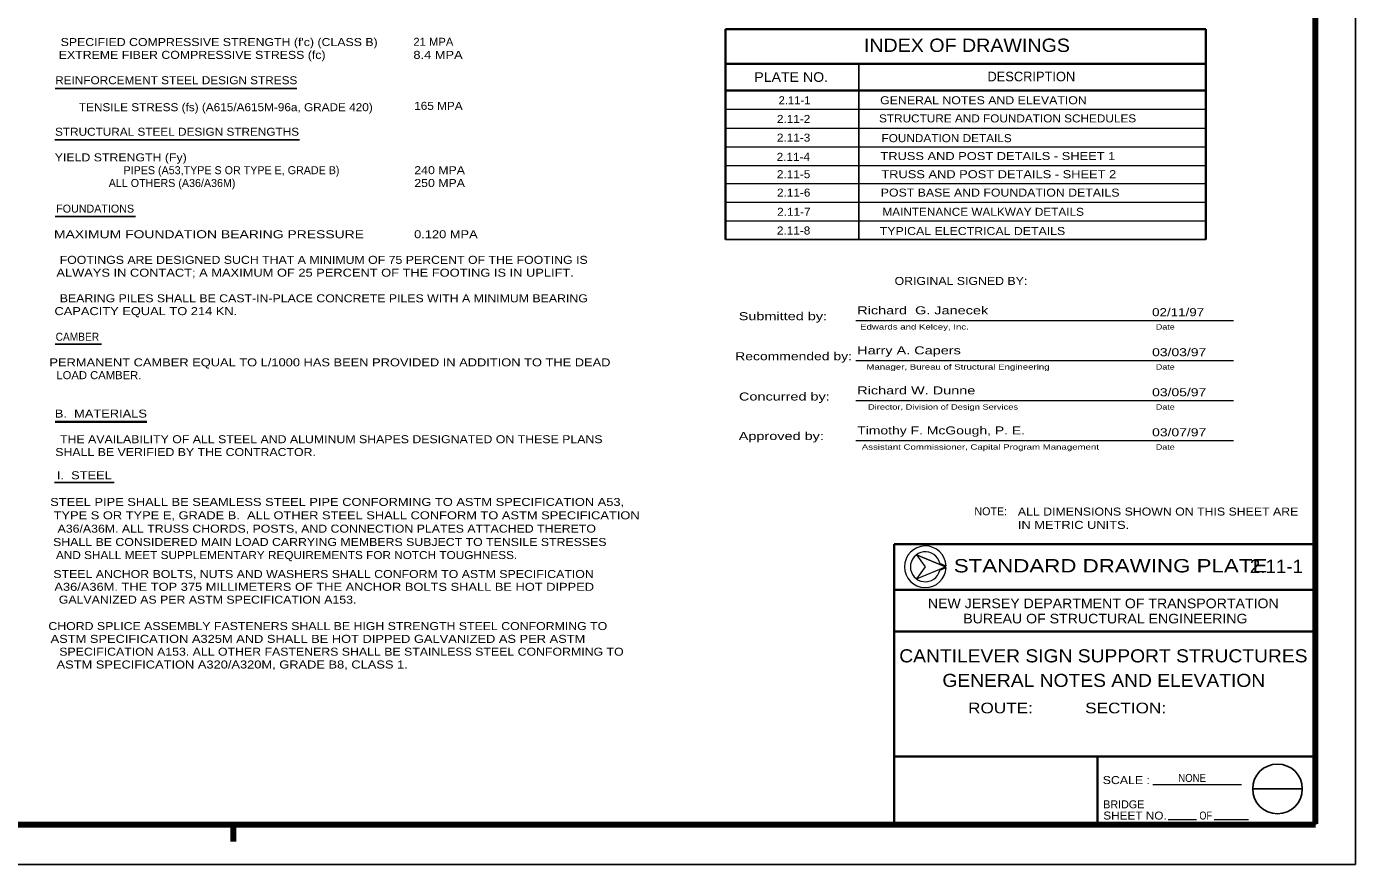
# Model space of a CAD drawing. Extents: x 312601.858 to 312602.699, y 144420.109 to 144420.704.
# Drawn here: x 312602.2008 to 312602.6988, y 144420.1095 to 144420.4234 of the extents above; entities that cross this region are included whole.
import ezdxf
from ezdxf.enums import TextEntityAlignment as Align

# ---------------------------------------------------------------- set-up
doc = ezdxf.new("R2010")
doc.units = 0
doc.header["$LTSCALE"] = 0.0012
for name, color, linetype, lineweight in [('1', 7, 'Continuous', 13), ('2', 7, 'Continuous', 25), ('39', 7, 'Continuous', 13)]:
    doc.layers.add(name, color=color, linetype=linetype, lineweight=lineweight)
doc.layers.add('4', color=7, linetype='Continuous')

msp = doc.modelspace()

# ---------------------------------------------------------------- linework, layer by layer
at = {"layer": '1', "lineweight": 35}
for p, q in [((312602.4627, 144420.4224), (312602.4627, 144420.3436)), ((312602.4627, 144420.4224), (312602.6427, 144420.4224)), ((312602.6427, 144420.4224), (312602.6427, 144420.3436)), ((312602.4627, 144420.4094), (312602.6427, 144420.4094)), ((312602.4627, 144420.3994), (312602.6427, 144420.3994))]:
    msp.add_line(p, q, dxfattribs=at)
at = {"layer": '1', "lineweight": 25}
for p, q in [((312602.5127, 144420.4094), (312602.5127, 144420.3436)), ((312602.4627, 144420.3436), (312602.6427, 144420.3436))]:
    msp.add_line(p, q, dxfattribs=at)
at = {"layer": '1'}
for p, q in [((312602.4627, 144420.3924), (312602.6427, 144420.3924)), ((312602.4627, 144420.3854), (312602.6427, 144420.3854)), ((312602.4627, 144420.3784), (312602.6427, 144420.3784)), ((312602.4627, 144420.3714), (312602.6427, 144420.3714)), ((312602.4627, 144420.3646), (312602.6427, 144420.3646)), ((312602.4627, 144420.3576), (312602.6427, 144420.3576)), ((312602.4627, 144420.3506), (312602.6427, 144420.3506)), ((312602.5116, 144420.3133), (312602.6531, 144420.3133)), ((312602.5116, 144420.2983), (312602.6531, 144420.2983)), ((312602.5116, 144420.2833), (312602.6531, 144420.2833)), ((312602.5116, 144420.2683), (312602.6531, 144420.2683)), ((312602.5431, 144420.2197), (312602.5454, 144420.2207)), ((312602.6286, 144420.1263), (312602.6392, 144420.1263)), ((312602.6459, 144420.1263), (312602.6587, 144420.1263))]:
    msp.add_line(p, q, dxfattribs=at)
for points in [[(312602.5452, 144420.221), (312602.5343, 144420.2255), (312602.5452, 144420.221)], [(312602.5454, 144420.2213), (312602.5431, 144420.2223), (312602.543, 144420.2223)]]:
    msp.add_lwpolyline(points, dxfattribs=at)
for points in [[(312602.5452, 144420.221), (312602.5343, 144420.2255), (312602.5375, 144420.221), (312602.5343, 144420.2165)], [(312602.5375, 144420.221), (312602.5343, 144420.2165), (312602.5452, 144420.221), (312602.5343, 144420.2255)]]:
    msp.add_lwpolyline(points, close=True, dxfattribs=at)
for radius, start, end in [(0.0078026, 2.21392, 357.78608), (0.0056, 13.69411, 346.30589)]:
    msp.add_arc((312602.5376, 144420.221), radius, start, end, dxfattribs=at)
at = {"layer": '2'}
for p, q in [((312602.2115, 144420.4002), (312602.3021, 144420.4002)), ((312602.2114, 144420.381), (312602.3031, 144420.381)), ((312602.2115, 144420.3523), (312602.2416, 144420.3523)), ((312602.2115, 144420.3044), (312602.2289, 144420.3044)), ((312602.6838, 144420.2674), (312602.6838, 144420.233)), ((312602.2113, 144420.2526), (312602.2336, 144420.2526))]:
    msp.add_line(p, q, dxfattribs=at)
at = {"layer": '2', "lineweight": 35}
msp.add_line((312602.2115, 144420.2753), (312602.2459, 144420.2753), dxfattribs=at)
at = {"layer": '39', "lineweight": 25}
for p, q in [((312602.6988, 144420.1095), (312602.6988, 144420.7035)), ((312602.6789, 144420.1378), (312602.6603, 144420.1378)), ((312601.8578, 144420.1095), (312602.6988, 144420.1095))]:
    msp.add_line(p, q, dxfattribs=at)
at = {"layer": '39', "lineweight": 158}
for p, q in [((312602.6838, 144420.1247), (312602.6838, 144420.6645)), ((312601.9088, 144420.1245), (312602.6838, 144420.1245)), ((312602.2783, 144420.1181), (312602.2783, 144420.1245))]:
    msp.add_line(p, q, dxfattribs=at)
at = {"layer": '39', "lineweight": 35}
for p, q in [((312602.526, 144420.1245), (312602.526, 144420.2295)), ((312602.526, 144420.2124), (312602.6838, 144420.2124)), ((312602.526, 144420.1968), (312602.6838, 144420.1968)), ((312602.526, 144420.1499), (312602.6838, 144420.1499)), ((312602.6022, 144420.1248), (312602.6022, 144420.1499)), ((312602.6022, 144420.1248), (312602.6022, 144420.1499))]:
    msp.add_line(p, q, dxfattribs=at)
at = {"layer": '39'}
for p, q in [((312602.6022, 144420.1499), (312602.6838, 144420.1499)), ((312602.6229, 144420.1395), (312602.6561, 144420.1395))]:
    msp.add_line(p, q, dxfattribs=at)
at = {"layer": '39', "lineweight": 35}
msp.add_lwpolyline([(312602.526, 144420.2295), (312602.6838, 144420.2295), (312602.6838, 144420.1245)], dxfattribs=at)
at = {"layer": '39'}
msp.add_lwpolyline([(312602.5452, 144420.221), (312602.5343, 144420.2255), (312602.5375, 144420.221), (312602.5343, 144420.2165)], close=True, dxfattribs=at)
at = {"layer": '39', "lineweight": 25}
msp.add_circle((312602.6696, 144420.1378), 0.0093005, dxfattribs=at)

# ---------------------------------------------------------------- texts
at = {"layer": '2'}
for s, height, width, p in [("SPECIFIED COMPRESSIVE STRENGTH (f'c) (CLASS B)              ", 0.003, 1.15, (312602.28195, 144420.4161)), ('21 MPA', 0.003, 1.05, (312602.35325, 144420.4162)), ('INDEX OF DRAWINGS', 0.005, 1.1, (312602.5532, 144420.4139)), ('EXTREME FIBER COMPRESSIVE STRESS (fc)            ', 0.003, 1.15, (312602.27055, 144420.4113)), ('8.4 MPA', 0.003, 1.2, (312602.355, 144420.4113)), ('REINFORCEMENT STEEL DESIGN STRESS', 0.003, 1.1, (312602.2569, 144420.4018)), ('PLATE NO.', 0.0036, 1.1, (312602.48735, 144420.4027)), ('2.11-1', 0.003, 1.05, (312602.4886, 144420.3943)), ('GENERAL NOTES AND ELEVATION', 0.003, 1.15, (312602.5594, 144420.3943)), ('TENSILE STRESS (fs) (A615/A615M-96a, GRADE 420)                         ', 0.003, 1.1, (312602.2908, 144420.3917)), ('165 MPA', 0.003, 1.1, (312602.35515, 144420.3922)), ('2.11-2', 0.003, 1.1, (312602.48825, 144420.3873)), ('STRUCTURE AND FOUNDATION SCHEDULES', 0.003, 1.1, (312602.56845, 144420.3875)), ('STRUCTURAL STEEL DESIGN STRENGTHS', 0.003, 1.1, (312602.2572, 144420.3825)), ('2.11-3', 0.003, 1.1, (312602.48825, 144420.3803)), ('FOUNDATION DETAILS', 0.003, 1.1, (312602.5456, 144420.3801)), ('YIELD STRENGTH (Fy)', 0.003, 1.15, (312602.2361, 144420.3729)), ('2.11-4', 0.003, 1.1, (312602.48815, 144420.3731)), ('TRUSS AND POST DETAILS - SHEET 1', 0.003, 1.2, (312602.5648, 144420.3734)), ('240 MPA', 0.003, 1.15, (312602.3556, 144420.3681)), ('2.11-5', 0.003, 1.1, (312602.48825, 144420.3666)), ('TRUSS AND POST DETAILS - SHEET 2', 0.003, 1.2, (312602.56515, 144420.3666)), ('250 MPA', 0.003, 1.15, (312602.3556, 144420.3633)), ('2.11-6', 0.003, 1.1, (312602.4883, 144420.3597)), ('POST BASE AND FOUNDATION DETAILS', 0.003, 1.15, (312602.56565, 144420.3597)), ('2.11-7', 0.003, 1.1, (312602.48835, 144420.3525)), ('MAINTENANCE WALKWAY DETAILS', 0.003, 1.1, (312602.5593, 144420.3525)), ('MAXIMUM FOUNDATION BEARING PRESSURE              ', 0.003, 1.3, (312602.2793, 144420.3441)), ('0.120 MPA', 0.003, 1.2, (312602.35795, 144420.3441)), ('2.11-8', 0.003, 1.1, (312602.48825, 144420.3455)), ('TYPICAL ELECTRICAL DETAILS', 0.003, 1.15, (312602.5553, 144420.3453)), ('FOOTINGS ARE DESIGNED SUCH THAT A MINIMUM OF 75 PERCENT OF THE FOOTING IS', 0.003, 1.15, (312602.31215, 144420.3345)), ('ALWAYS IN CONTACT; A MAXIMUM OF 25 PERCENT OF THE FOOTING IS IN UPLIFT.', 0.003, 1.2, (312602.30895, 144420.3297)), ('BEARING PILES SHALL BE CAST-IN-PLACE CONCRETE PILES WITH A MINIMUM BEARING', 0.003, 1.15, (312602.3122, 144420.3201)), ('CAPACITY EQUAL TO 214 KN.', 0.003, 1.2, (312602.2455, 144420.3153)), ('Submitted by:', 0.003, 1.35, (312602.48425, 144420.3134)), ('CAMBER', 0.003, 0.95, (312602.21985, 144420.3057)), ('Edwards and Kelcey, Inc.', 0.002, 1.35, (312602.53355, 144420.3099)), ('Date', 0.002, 1.25, (312602.62755, 144420.3099)), ('PERMANENT CAMBER EQUAL TO L/1000 HAS BEEN PROVIDED IN ADDITION TO THE DEAD', 0.003, 1.2, (312602.3145, 144420.2961)), ('Recommended by:', 0.003, 1.3, (312602.48825, 144420.2984)), ('LOAD CAMBER.', 0.003, 1.05, (312602.2279, 144420.2913)), ('Manager, Bureau of Structural Engineering', 0.002, 1.35, (312602.54985, 144420.2949)), ('Date', 0.002, 1.25, (312602.62755, 144420.2949)), ('Concurred by:', 0.003, 1.35, (312602.4848, 144420.2833)), ('B.  MATERIALS', 0.003, 1.2, (312602.22865, 144420.2769)), ('Director, Division of Design Services', 0.002, 1.3, (312602.54425, 144420.2799)), ('Date', 0.002, 1.25, (312602.62755, 144420.2799)), ('THE AVAILABILITY OF ALL STEEL AND ALUMINUM SHAPES DESIGNATED ON THESE PLANS', 0.003, 1.15, (312602.315, 144420.2673)), ('Approved by:', 0.003, 1.35, (312602.48365, 144420.2685)), ('SHALL BE VERIFIED BY THE CONTRACTOR.', 0.003, 1.15, (312602.2604, 144420.2625)), ('Assistant Commissioner, Capital Program Management', 0.002, 1.35, (312602.55825, 144420.2649)), ('Date', 0.002, 1.25, (312602.62755, 144420.2649)), ('I.  STEEL', 0.003, 1.2, (312602.22245, 144420.2538)), ('STEEL PIPE SHALL BE SEAMLESS STEEL PIPE CONFORMING TO ASTM SPECIFICATION A53,', 0.003, 1.2, (312602.3172, 144420.2438)), ('TYPE S OR TYPE E, GRADE B.  ALL OTHER STEEL SHALL CONFORM TO ASTM SPECIFICATION', 0.003, 1.2, (312602.32075, 144420.2388)), ('A36/A36M. ALL TRUSS CHORDS, POSTS, AND CONNECTION PLATES ATTACHED THERETO', 0.003, 1.15, (312602.3133, 144420.2338)), ('SHALL BE CONSIDERED MAIN LOAD CARRYING MEMBERS SUBJECT TO TENSILE STRESSES', 0.003, 1.15, (312602.31445, 144420.2288)), ('AND SHALL MEET SUPPLEMENTARY REQUIREMENTS FOR NOTCH TOUGHNESS.', 0.003, 1.1, (312602.29825, 144420.2239)), ('2.11-1', 0.005, 1.05, (312602.6692, 144420.2187)), ('STEEL ANCHOR BOLTS, NUTS AND WASHERS SHALL CONFORM TO ASTM SPECIFICATION', 0.003, 1.15, (312602.3121, 144420.2168)), ('A36/A36M. THE TOP 375 MILLIMETERS OF THE ANCHOR BOLTS SHALL BE HOT DIPPED', 0.003, 1.2, (312602.31235, 144420.212)), ('GALVANIZED AS PER ASTM SPECIFICATION A153.', 0.003, 1.15, (312602.26865, 144420.2072)), ('CHORD SPLICE ASSEMBLY FASTENERS SHALL BE HIGH STRENGTH STEEL CONFORMING TO', 0.003, 1.15, (312602.3137, 144420.1973)), ('ASTM SPECIFICATION A325M AND SHALL BE HOT DIPPED GALVANIZED AS PER ASTM', 0.003, 1.2, (312602.31, 144420.1925)), ('SPECIFICATION A153. ALL OTHER FASTENERS SHALL BE STAINLESS STEEL CONFORMING TO ', 0.003, 1.15, (312602.31945, 144420.1877)), ('CANTILEVER SIGN SUPPORT STRUCTURES', 0.0049, 1.1, (312602.60435, 144420.1852)), ('ASTM SPECIFICATION A320/A320M, GRADE B8, CLASS 1.', 0.003, 1.2, (312602.27785, 144420.1829)), ('GENERAL NOTES AND ELEVATION', 0.0049, 1.1, (312602.6045, 144420.176)), ('NONE', 0.003, 0.9, (312602.6376, 144420.1404))]:
    msp.add_text(s, height=height, dxfattribs=dict(at, width=width)).set_placement(p, align=Align.CENTER)
for s, height, p in [('DESCRIPTION', 0.0036, (312602.57735, 144420.4029)), ('     PIPES (A53,TYPE S OR TYPE E, GRADE B)                                        ', 0.003, (312602.2971, 144420.3681)), ('     ALL OTHERS (A36/A36M)                                  ', 0.003, (312602.2715, 144420.3633)), ('FOUNDATIONS', 0.003, (312602.2265, 144420.3537))]:
    msp.add_text(s, height=height, dxfattribs=at).set_placement(p, align=Align.CENTER)
at = {"layer": '39'}
for s, height, width, p in [('STANDARD DRAWING PLATE       ', 0.005, 1.25, (312602.61515, 144420.2189)), ('NEW JERSEY DEPARTMENT OF TRANSPORTATION', 0.003599, 1.1, (312602.6043, 144420.2055)), ('BUREAU OF STRUCTURAL ENGINEERING', 0.0036, 1.1, (312602.6051, 144420.1998)), ('ROUTE:           SECTION:', 0.004, 1.2, (312602.59075, 144420.1661)), ('SCALE :', 0.003, 1.15, (312602.61295, 144420.1396)), ('SCALE :', 0.003, 1.15, (312602.61295, 144420.1396)), ('SCALE :', 0.003, 1.15, (312602.61295, 144420.1396)), ('OF', 0.003, 0.85, (312602.6427, 144420.1263))]:
    msp.add_text(s, height=height, dxfattribs=dict(at, width=width)).set_placement(p, align=Align.CENTER)
msp.add_text('BRIDGE', height=0.003, dxfattribs=at).set_placement((312602.6043, 144420.1305))
msp.add_text('BRIDGE', height=0.003, dxfattribs=at).set_placement((312602.6043, 144420.1305))
msp.add_text('BRIDGE', height=0.003, dxfattribs=at).set_placement((312602.6043, 144420.1305))
at = {"layer": '39', "width": 1.1}
msp.add_text('SHEET NO.', height=0.003, dxfattribs=at).set_placement((312602.6043, 144420.1263))
msp.add_text('SHEET NO.', height=0.003, dxfattribs=at).set_placement((312602.6043, 144420.1263))
msp.add_text('SHEET NO.', height=0.003, dxfattribs=at).set_placement((312602.6043, 144420.1263))
at = {"layer": '4'}
for s, width, p in [('ORIGINAL SIGNED BY:', 1.15, (312602.5261, 144420.3266)), ('Richard  G. Janecek', 1.35, (312602.5121, 144420.3156)), ('02/11/97', 1.25, (312602.6226, 144420.3149)), ('Harry A. Capers', 1.35, (312602.5121, 144420.3006)), ('03/03/97', 1.3, (312602.6226, 144420.2999)), ('Richard W. Dunne', 1.35, (312602.5121, 144420.2856)), ('03/05/97', 1.3, (312602.6226, 144420.2849)), ('Timothy F. McGough, P. E.', 1.3, (312602.5121, 144420.2706)), ('03/07/97', 1.3, (312602.6226, 144420.2699)), ('ALL DIMENSIONS SHOWN ON THIS SHEET ARE', 1.15, (312602.5723, 144420.2402)), ('IN METRIC UNITS.', 1.2, (312602.5723, 144420.2352))]:
    msp.add_text(s, height=0.003, dxfattribs=dict(at, width=width)).set_placement(p)
msp.add_text('NOTE:', height=0.003, dxfattribs=at).set_placement((312602.556, 144420.2403))

doc.saveas('drawing.dxf')
